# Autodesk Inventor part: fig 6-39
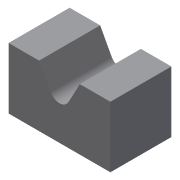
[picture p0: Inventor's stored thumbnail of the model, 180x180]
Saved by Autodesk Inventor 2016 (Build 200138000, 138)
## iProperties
Created: 2005-12
Part Number: fig 6-39
Document SubType Name: Modeling
Designer: CADCIM
Density: 1 g/cm^3
Material: Generic
Appearance: Default
Author: CADCIM
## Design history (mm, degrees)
sketch "Sketch1"
  geometry: L1 (10, 15)-(25, 15); L2 (25, 15)-(25, -15); L3 (25, -15)-(-25, -15); L4 (-25, -15)-(-25, 15); L5 (-25, 15)-(-10, 15); L6 (-10, 15)-(-2, 0); L7 (-2, 0)-(2, 0); L8 (2, 0)-(10, 15); 1 further point
  constraints: 16 end point, 3 equal length, 3 parallel, 1 collinear, 1 horizontal, 1 perpendicular, 1 other
  dimensions: "d0" = 50 distance of L2.end L3.end; "d1" = 25 distance from line of point (0, 0) L2; "d2" = 30 distance of L1.end L2.end; "d3" = 15 distance of L1.start L1.end; "d4" = 15 distance between parallel lines of L1 L7; "d5" = 4 distance of L6.end L7.end; "d6" = 15 distance from line of point (0, 0) L3
extrude "Extrusion1" new body sketch "Sketch1" stored distance "d7" = 30; taper "d8" = 0 deg
fillet "Fillet4" dims "d11" = 5
body "Solid1"
